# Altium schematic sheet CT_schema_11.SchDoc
size 405 x 220 mm
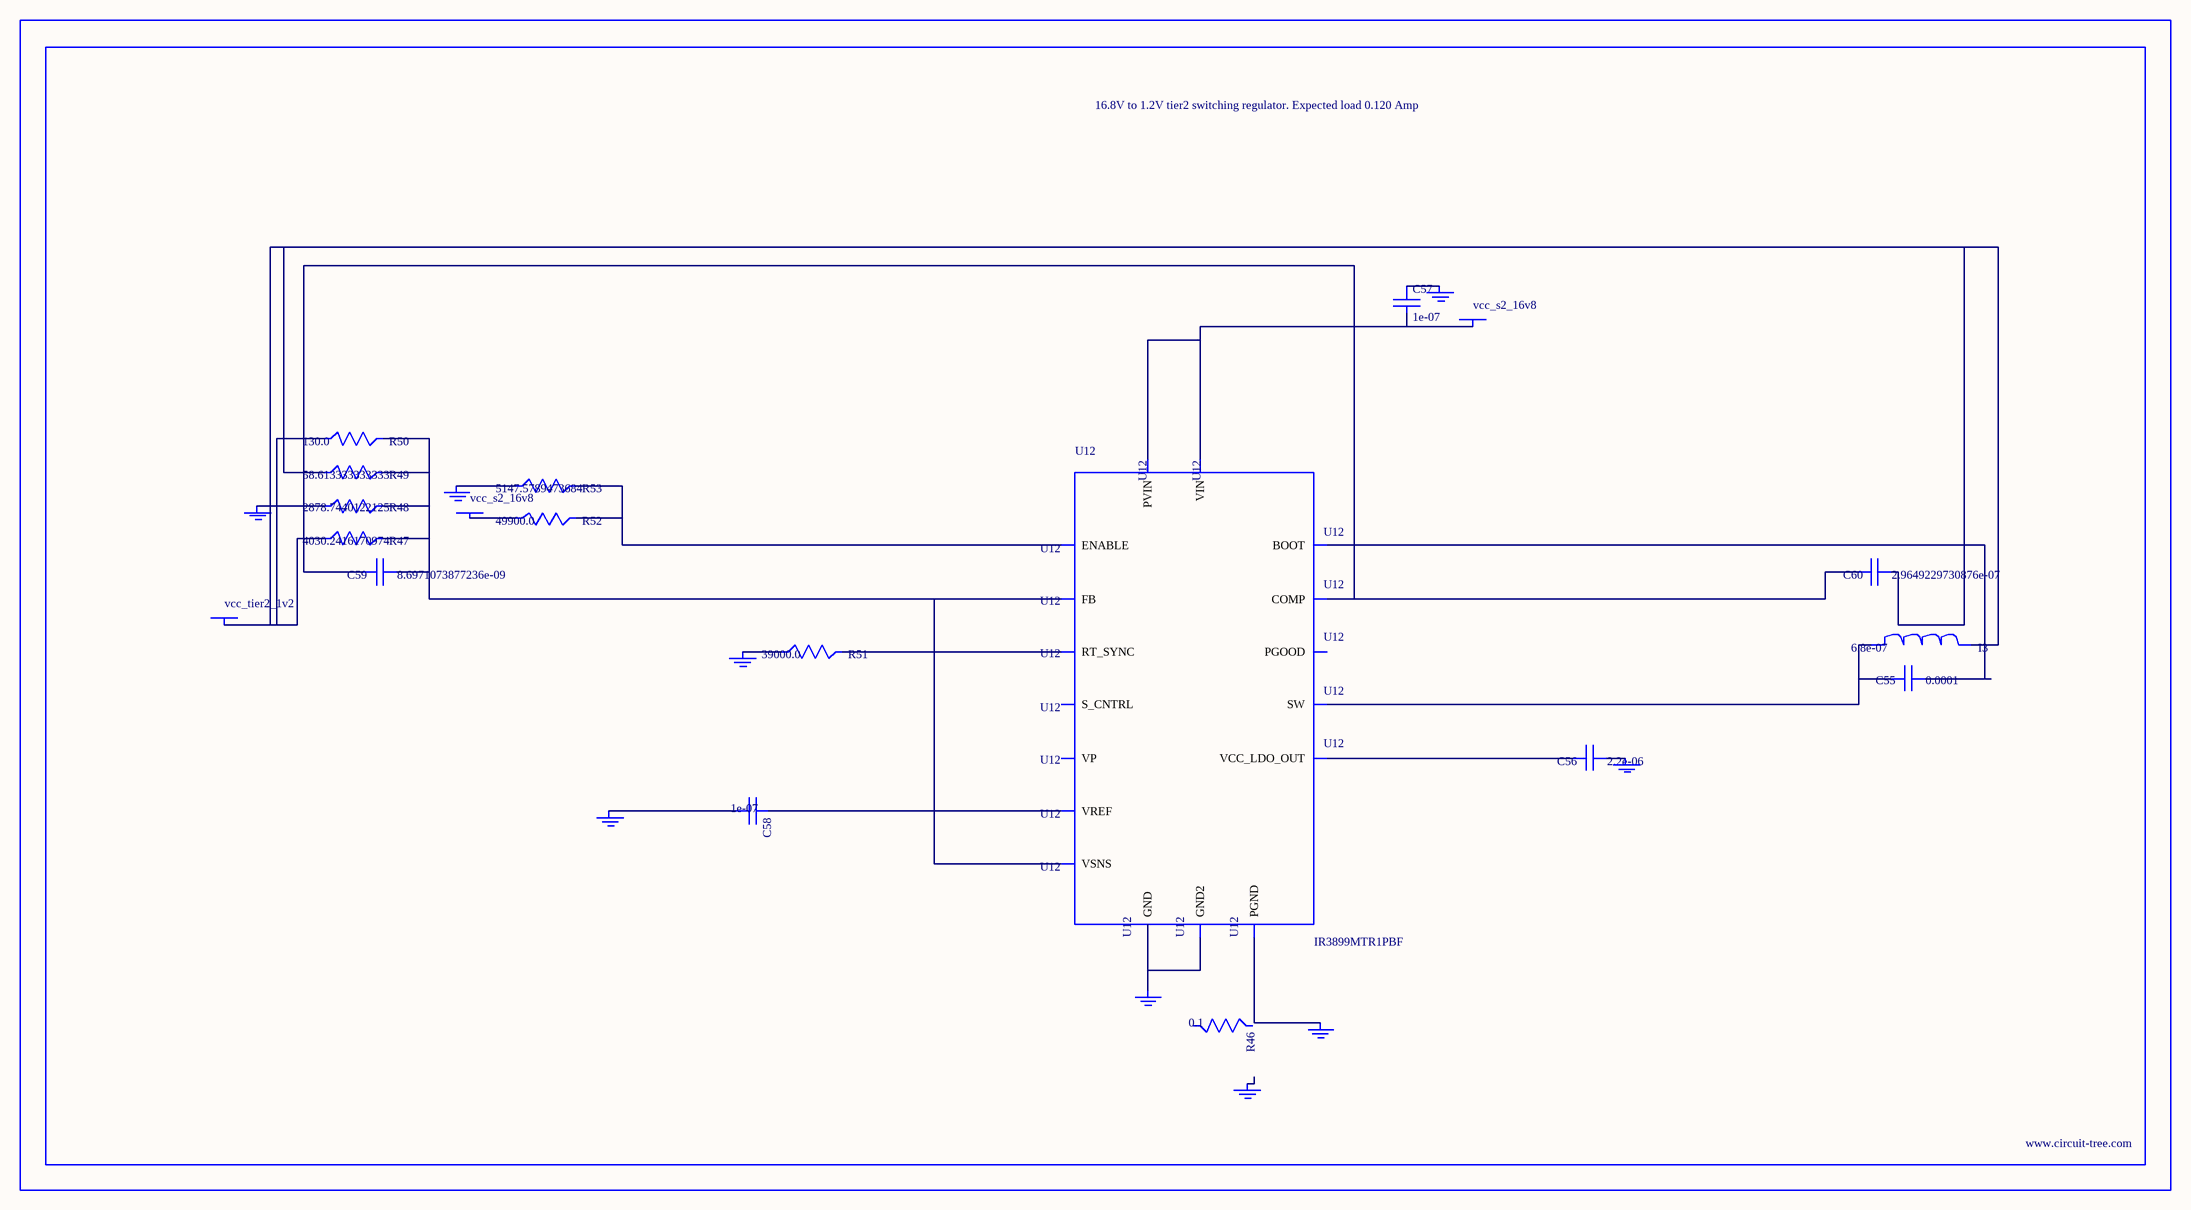
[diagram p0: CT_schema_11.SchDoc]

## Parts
BORDER10  (no value)
C55  0.0001  [C1210]
C56  2.2e-06  [C0603]
C57  1e-07  [C0402]
C58  1e-07  [C0402]
C59  8.6971073877236e-09  [R0603]
C60  2.9649229730876e-07  [R0603]
GND_INSTANCE_10_0  (no value)
GND_INSTANCE_10_1  (no value)
GND_INSTANCE_10_2  (no value)
GND_INSTANCE_10_3  (no value)
GND_INSTANCE_10_4  (no value)
GND_INSTANCE_10_5  (no value)
GND_INSTANCE_10_6  (no value)
GND_INSTANCE_10_7  (no value)
GND_INSTANCE_10_8  (no value)
I3  6.8e-07  [IND25X25CZ]
POWER_INSTANCE_10_0  vcc_s2_16v8
POWER_INSTANCE_10_1  vcc_s2_16v8
POWER_INSTANCE_10_2  vcc_tier2_1v2
R46  0.1  [R0603]
R47  4030.2416170974  [R0603]
R48  2878.7440122125  [R0603]
R49  58.613333333333  [R0603]
R50  130.0  [R0603]
R51  39000.0  [R0603]
R52  49900.0  [R0603]
R53  5147.5789473684  [R0603]
U12  IR3899MTR1PBF  [IR3899MTR1PBF]

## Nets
NetC55_1: C55.1 U12.14(BOOT)
NetC55_2: C55.2 I3.1 U12.12(SW)
NetC56_1: C56.1 GND_INSTANCE_10_4.0(GND)
NetC56_2: C56.2 U12.10(VCC_LDO_OUT)
NetC57_1: C57.1 GND_INSTANCE_10_3.0(GND)
NetC57_2: C57.2 POWER_INSTANCE_10_0.0(PWR) U12.9(VIN) U12.13(PVIN)
NetC58_1: C58.1 U12.2(VREF)
NetC58_2: C58.2 GND_INSTANCE_10_1.0(GND)
NetC59_1: C59.1 R47.2 R48.2 R49.2 R50.2 U12.1(FB) U12.8(VSNS)
NetC59_2: C59.2 C60.2 U12.3(COMP)
NetC60_1: C60.1 I3.2 POWER_INSTANCE_10_2.0(PWR) R47.1 R49.1 R50.1
NetGND_INSTANCE_10_0_0: GND_INSTANCE_10_0.0(GND) R48.1
NetGND_INSTANCE_10_2_0: GND_INSTANCE_10_2.0(GND) R51.1
NetGND_INSTANCE_10_6_0: GND_INSTANCE_10_6.0(GND) U12.11(PGND)
NetGND_INSTANCE_10_7_0: GND_INSTANCE_10_7.0(GND) R53.1
NetGND_INSTANCE_10_8_0: GND_INSTANCE_10_8.0(GND) U12.4(GND) U12.17(GND2)
NetPOWER_INSTANCE_10_1_0: POWER_INSTANCE_10_1.0(PWR) R52.1
NetR51_2: R51.2 U12.5(RT_SYNC)
NetR52_2: R52.2 R53.2 U12.15(ENABLE)

Not connected (* = marked no-connect by the designer): GND_INSTANCE_10_5 0(GND); R46 1 2; U12 6(S_CNTRL) 7(PGOOD) 16(VP)

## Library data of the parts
BORDER10 = BORDER_PAGE10
C55 = GRM32ER61A107ME20L
C56 = C0603C225K8RACTU
C57 C58 = C0402C104K3RACTU
C59 = C59
C60 = C60
GND_INSTANCE_10_0-GND_INSTANCE_10_8 = GND
I3 = IHLP2525CZERR68M01
POWER_INSTANCE_10_0-POWER_INSTANCE_10_2 = PWR
R46 = ERJ-3RSFR10V
R47 = R47
R48 = R48
R49 = R49
R50 = RC0603JR-07130RL
R51 = RC0603JR-0739KL
R52 = RC0603FR-0749K9
R53 = R53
